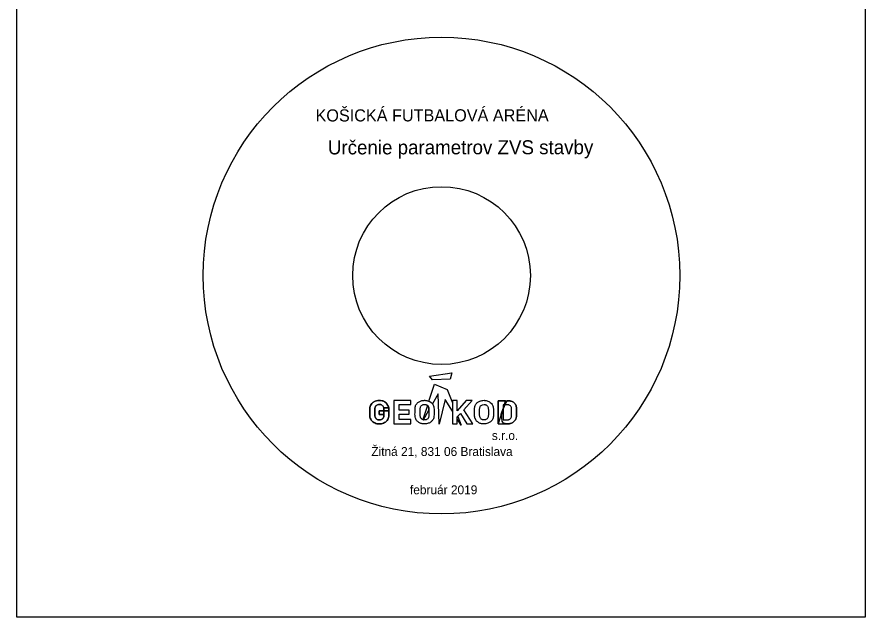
# Model space of a CAD drawing. Extents: x -505246 to -505036, y -1268489 to -1268192.
# Drawn here: x -505246.3 to -505036.3, y -1268489.2 to -1268340.7 of the extents above; entities that cross this region are included whole.
import ezdxf

# ---------------------------------------------------------------- set-up
doc = ezdxf.new("R2010")
doc.units = 0
for name, color, linetype in [('CD_KRUHY', 7, 'Continuous'), ('CD_POPIS', 7, 'Continuous'), ('RAM_NA_TLAC_A4', 7, 'Continuous')]:
    doc.layers.add(name, color=color, linetype=linetype)

msp = doc.modelspace()

# ---------------------------------------------------------------- linework, layer by layer
at = {"layer": 'CD_KRUHY'}
for radius in [59, 22]:
    msp.add_circle((-505141.22, -1268404.66), radius, dxfattribs=at)
at = {"layer": 'CD_POPIS'}
for p, q in [((-505144.36, -1268435.74), (-505142.96, -1268431.5)), ((-505142.96, -1268431.5), (-505139.85, -1268432.82)), ((-505139.85, -1268432.82), (-505138.54, -1268436.16)), ((-505145.5, -1268435.54), (-505145.4, -1268435.53)), ((-505142.07, -1268433.91), (-505143.47, -1268436.41)), ((-505141.8, -1268441.47), (-505142.07, -1268433.91)), ((-505140.31, -1268435.35), (-505141.8, -1268441.47)), ((-505138.54, -1268438.19), (-505140.31, -1268435.35)), ((-505137.32, -1268435.61), (-505138.54, -1268435.61)), ((-505135.12, -1268435.61), (-505137.32, -1268438.11)), ((-505137.32, -1268438.11), (-505137.32, -1268435.61)), ((-505135.7, -1268437.91), (-505133.6, -1268435.61)), ((-505133.6, -1268435.61), (-505135.12, -1268435.61)), ((-505127.18, -1268435.63), (-505125.35, -1268435.63)), ((-505127.18, -1268441.33), (-505127.18, -1268435.63)), ((-505127.18, -1268435.63), (-505127.18, -1268441.33)), ((-505125.35, -1268435.63), (-505127.18, -1268435.63)), ((-505154.25, -1268437.38), (-505155.51, -1268437.38)), ((-505155.51, -1268437.38), (-505154.25, -1268437.38)), ((-505144.71, -1268436.79), (-505145.87, -1268440.31)), ((-505145.48, -1268436.56), (-505145.41, -1268436.56)), ((-505145.48, -1268436.56), (-505145.41, -1268436.56)), ((-505138.54, -1268436.16), (-505138.54, -1268438.19)), ((-505125.93, -1268436.62), (-505125.93, -1268440.34)), ((-505125.93, -1268436.62), (-505125.93, -1268440.34)), ((-505137.22, -1268439.51), (-505136.37, -1268441.69)), ((-505133.49, -1268441.33), (-505135.7, -1268437.91)), ((-505136.37, -1268441.69), (-505137.32, -1268440.15)), ((-505134.93, -1268441.33), (-505133.49, -1268441.33))]:
    msp.add_line(p, q, dxfattribs=at)
for points in [[(-505144.2, -1268429.53), (-505138.67, -1268428.74), (-505139.06, -1268430.32), (-505143.47, -1268430.46)], [(-505152.99, -1268435.58), (-505152.99, -1268441.33), (-505148.78, -1268441.33), (-505148.78, -1268440.32), (-505151.73, -1268440.32), (-505151.73, -1268438.94), (-505149.21, -1268438.94), (-505149.21, -1268437.94), (-505151.73, -1268437.94), (-505151.73, -1268436.6), (-505148.78, -1268436.6), (-505148.78, -1268435.58)]]:
    msp.add_lwpolyline(points, close=True, dxfattribs=at)
for points in [[(-505138.54, -1268435.61), (-505138.54, -1268441.33), (-505137.32, -1268441.33), (-505137.32, -1268439.62), (-505136.51, -1268438.76), (-505134.93, -1268441.33)], [(-505144.33, -1268437.96), (-505144.33, -1268437.83), (-505144.34, -1268437.67), (-505144.35, -1268437.53), (-505144.37, -1268437.39), (-505144.41, -1268437.26), (-505144.46, -1268437.12), (-505144.53, -1268436.99), (-505144.62, -1268436.88), (-505144.71, -1268436.79)], [(-505143.47, -1268436.41), (-505143.51, -1268436.36), (-505143.58, -1268436.27), (-505143.65, -1268436.2), (-505143.74, -1268436.13), (-505143.82, -1268436.06), (-505143.91, -1268435.99), (-505143.99, -1268435.94), (-505144.08, -1268435.89), (-505144.18, -1268435.83), (-505144.27, -1268435.78), (-505144.36, -1268435.74)], [(-505155.47, -1268439.07), (-505156.67, -1268439.07), (-505156.67, -1268438.12), (-505154.23, -1268438.12)], [(-505154.23, -1268438.12), (-505156.67, -1268438.12), (-505156.67, -1268439.07), (-505155.47, -1268439.07)], [(-505145.68, -1268440.36), (-505144.33, -1268437.96)], [(-505137.32, -1268440.15), (-505137.32, -1268439.62), (-505137.22, -1268439.51)], [(-505145.87, -1268440.31), (-505145.84, -1268440.32), (-505145.8, -1268440.33), (-505145.77, -1268440.34), (-505145.73, -1268440.35), (-505145.7, -1268440.36), (-505145.68, -1268440.36)]]:
    msp.add_lwpolyline(points, dxfattribs=at)
for points in [[(-505154.23, -1268438.12), (-505154.23, -1268438.85), (-505154.25, -1268439.5), (-505154.38, -1268440.08), (-505154.66, -1268440.54), (-505155.08, -1268440.93), (-505155.53, -1268441.19), (-505156.12, -1268441.34), (-505156.66, -1268441.38), (-505157.22, -1268441.34), (-505157.78, -1268441.15), (-505158.26, -1268440.84), (-505158.63, -1268440.47), (-505158.88, -1268439.96), (-505158.99, -1268439.41), (-505159.01, -1268439.04), (-505159.01, -1268437.9), (-505158.97, -1268437.29), (-505158.8, -1268436.77), (-505158.52, -1268436.32), (-505157.97, -1268435.87), (-505157.37, -1268435.61), (-505156.68, -1268435.54), (-505155.96, -1268435.6), (-505155.19, -1268435.91), (-505154.6, -1268436.47), (-505154.25, -1268437.38), (-505154.23, -1268438.12), (-505154.25, -1268437.38)], [(-505154.25, -1268437.38), (-505154.6, -1268436.47), (-505155.19, -1268435.91), (-505155.96, -1268435.6), (-505156.68, -1268435.54), (-505157.37, -1268435.61), (-505157.97, -1268435.87), (-505158.52, -1268436.32), (-505158.8, -1268436.77), (-505158.97, -1268437.29), (-505159.01, -1268437.9), (-505159.01, -1268439.04), (-505158.99, -1268439.41), (-505158.88, -1268439.96), (-505158.63, -1268440.47), (-505158.26, -1268440.84), (-505157.78, -1268441.15), (-505157.22, -1268441.34), (-505156.66, -1268441.38), (-505156.12, -1268441.34), (-505155.53, -1268441.19), (-505155.08, -1268440.93), (-505154.66, -1268440.54), (-505154.38, -1268440.08), (-505154.25, -1268439.5), (-505154.23, -1268438.85), (-505154.23, -1268438.12), (-505154.25, -1268437.38), (-505154.23, -1268438.12)], [(-505145.4, -1268435.53), (-505145.37, -1268435.53), (-505145.2, -1268435.53), (-505144.88, -1268435.61), (-505144.45, -1268435.68), (-505144.04, -1268435.91), (-505143.67, -1268436.16), (-505143.37, -1268436.52), (-505143.19, -1268436.92), (-505143.08, -1268437.36), (-505143.08, -1268438.05), (-505143.06, -1268438.77), (-505143.08, -1268439.46), (-505143.14, -1268439.91), (-505143.31, -1268440.27), (-505143.52, -1268440.6), (-505143.81, -1268440.85), (-505144.12, -1268441.08), (-505144.5, -1268441.23), (-505144.92, -1268441.36), (-505145.38, -1268441.38), (-505145.81, -1268441.36), (-505146.19, -1268441.32), (-505146.51, -1268441.17), (-505146.82, -1268441), (-505147.12, -1268440.8), (-505147.39, -1268440.53), (-505147.6, -1268440.15), (-505147.75, -1268439.7), (-505147.82, -1268438.95), (-505147.75, -1268438.25), (-505147.79, -1268437.58), (-505147.73, -1268437.2), (-505147.64, -1268436.83), (-505147.46, -1268436.5), (-505147.22, -1268436.22), (-505146.96, -1268435.98), (-505146.63, -1268435.81), (-505146.26, -1268435.64), (-505145.87, -1268435.56), (-505145.61, -1268435.54), (-505145.5, -1268435.54)], [(-505130.68, -1268435.53), (-505131.11, -1268435.56), (-505131.56, -1268435.66), (-505131.93, -1268435.82), (-505132.23, -1268435.99), (-505132.5, -1268436.23), (-505132.72, -1268436.49), (-505132.91, -1268436.84), (-505133.01, -1268437.21), (-505133.06, -1268437.57), (-505133.05, -1268437.97), (-505133.07, -1268439.21), (-505133.02, -1268439.67), (-505132.85, -1268440.18), (-505132.64, -1268440.54), (-505132.41, -1268440.78), (-505132.09, -1268441), (-505131.79, -1268441.17), (-505131.48, -1268441.3), (-505131.1, -1268441.36), (-505130.69, -1268441.38), (-505130.2, -1268441.34), (-505129.76, -1268441.22), (-505129.42, -1268441.07), (-505129.08, -1268440.84), (-505128.81, -1268440.59), (-505128.61, -1268440.29), (-505128.44, -1268439.9), (-505128.37, -1268439.49), (-505128.35, -1268438.99), (-505128.36, -1268437.81), (-505128.38, -1268437.35), (-505128.48, -1268436.94), (-505128.68, -1268436.51), (-505128.94, -1268436.2), (-505129.35, -1268435.9), (-505129.73, -1268435.71), (-505130.17, -1268435.6), (-505130.6, -1268435.53), (-505130.68, -1268435.53), (-505130.68, -1268435.53), (-505130.68, -1268435.53)], [(-505125.35, -1268435.63), (-505124.76, -1268435.63), (-505124.39, -1268435.65), (-505124.11, -1268435.7), (-505123.76, -1268435.82), (-505123.42, -1268436.01), (-505123.08, -1268436.33), (-505122.83, -1268436.69), (-505122.71, -1268437.03), (-505122.63, -1268437.55), (-505122.63, -1268437.81), (-505122.62, -1268438.95), (-505122.64, -1268439.32), (-505122.67, -1268439.63), (-505122.72, -1268439.95), (-505122.88, -1268440.35), (-505123.17, -1268440.71), (-505123.59, -1268441.05), (-505123.93, -1268441.2), (-505124.28, -1268441.3), (-505124.57, -1268441.33), (-505124.68, -1268441.33), (-505127.18, -1268441.33), (-505125.35, -1268435.63), (-505127.18, -1268441.33)], [(-505127.18, -1268441.33), (-505124.68, -1268441.33), (-505124.57, -1268441.33), (-505124.28, -1268441.3), (-505123.93, -1268441.2), (-505123.59, -1268441.05), (-505123.17, -1268440.71), (-505122.88, -1268440.35), (-505122.72, -1268439.95), (-505122.67, -1268439.63), (-505122.64, -1268439.32), (-505122.62, -1268438.95), (-505122.63, -1268437.81), (-505122.63, -1268437.55), (-505122.71, -1268437.03), (-505122.83, -1268436.69), (-505123.08, -1268436.33), (-505123.42, -1268436.01), (-505123.76, -1268435.82), (-505124.11, -1268435.7), (-505124.39, -1268435.65), (-505124.76, -1268435.63), (-505125.35, -1268435.63), (-505127.18, -1268441.33), (-505125.35, -1268435.63)], [(-505155.5, -1268437.38), (-505155.63, -1268437.07), (-505155.9, -1268436.76), (-505156.29, -1268436.58), (-505156.67, -1268436.56), (-505157.05, -1268436.6), (-505157.35, -1268436.78), (-505157.58, -1268437.02), (-505157.69, -1268437.28), (-505157.7, -1268437.67), (-505157.73, -1268438.1), (-505157.74, -1268438.61), (-505157.73, -1268439.21), (-505157.68, -1268439.66), (-505157.51, -1268440.01), (-505157.27, -1268440.22), (-505156.98, -1268440.34), (-505156.68, -1268440.38), (-505156.31, -1268440.36), (-505155.93, -1268440.2), (-505155.66, -1268439.94), (-505155.5, -1268439.64), (-505155.47, -1268439.3), (-505155.47, -1268439.07), (-505155.5, -1268437.38), (-505155.47, -1268439.07)], [(-505155.47, -1268439.07), (-505155.47, -1268439.3), (-505155.5, -1268439.64), (-505155.66, -1268439.94), (-505155.93, -1268440.2), (-505156.31, -1268440.36), (-505156.68, -1268440.38), (-505156.98, -1268440.34), (-505157.27, -1268440.22), (-505157.51, -1268440.01), (-505157.68, -1268439.66), (-505157.73, -1268439.21), (-505157.74, -1268438.61), (-505157.73, -1268438.1), (-505157.7, -1268437.67), (-505157.69, -1268437.28), (-505157.58, -1268437.02), (-505157.35, -1268436.78), (-505157.05, -1268436.6), (-505156.67, -1268436.56), (-505156.29, -1268436.58), (-505155.9, -1268436.76), (-505155.63, -1268437.07), (-505155.5, -1268437.38), (-505155.47, -1268439.07), (-505155.5, -1268437.38)], [(-505145.41, -1268436.56), (-505145.36, -1268436.56), (-505145.23, -1268436.56), (-505145, -1268436.61), (-505144.75, -1268436.74), (-505144.52, -1268436.96), (-505144.38, -1268437.28), (-505144.32, -1268437.63), (-505144.33, -1268438.02), (-505144.32, -1268438.43), (-505144.34, -1268438.85), (-505144.32, -1268439.23), (-505144.37, -1268439.56), (-505144.45, -1268439.86), (-505144.63, -1268440.12), (-505144.91, -1268440.3), (-505145.2, -1268440.38), (-505145.44, -1268440.36), (-505145.65, -1268440.38), (-505145.88, -1268440.32), (-505146.11, -1268440.18), (-505146.33, -1268439.97), (-505146.48, -1268439.66), (-505146.53, -1268439.29), (-505146.51, -1268438.83), (-505146.52, -1268438.33), (-505146.51, -1268437.85), (-505146.5, -1268437.45), (-505146.43, -1268437.14), (-505146.26, -1268436.89), (-505146.03, -1268436.69), (-505145.75, -1268436.57), (-505145.56, -1268436.56), (-505145.48, -1268436.56)], [(-505145.41, -1268436.56), (-505145.36, -1268436.56), (-505145.23, -1268436.56), (-505145, -1268436.61), (-505144.75, -1268436.74), (-505144.52, -1268436.96), (-505144.38, -1268437.28), (-505144.32, -1268437.63), (-505144.33, -1268438.02), (-505144.32, -1268438.43), (-505144.34, -1268438.85), (-505144.32, -1268439.23), (-505144.37, -1268439.56), (-505144.45, -1268439.86), (-505144.63, -1268440.12), (-505144.91, -1268440.3), (-505145.2, -1268440.38), (-505145.44, -1268440.36), (-505145.65, -1268440.38), (-505145.88, -1268440.32), (-505146.11, -1268440.18), (-505146.33, -1268439.97), (-505146.48, -1268439.66), (-505146.53, -1268439.29), (-505146.51, -1268438.83), (-505146.52, -1268438.33), (-505146.51, -1268437.85), (-505146.5, -1268437.45), (-505146.43, -1268437.14), (-505146.26, -1268436.89), (-505146.03, -1268436.69), (-505145.75, -1268436.57), (-505145.56, -1268436.56), (-505145.48, -1268436.56)], [(-505130.7, -1268436.56), (-505131, -1268436.58), (-505131.31, -1268436.71), (-505131.54, -1268436.91), (-505131.69, -1268437.13), (-505131.77, -1268437.45), (-505131.79, -1268437.79), (-505131.8, -1268438.31), (-505131.8, -1268438.9), (-505131.8, -1268439.3), (-505131.74, -1268439.66), (-505131.58, -1268439.97), (-505131.38, -1268440.18), (-505131.16, -1268440.31), (-505130.92, -1268440.37), (-505130.72, -1268440.37), (-505130.52, -1268440.37), (-505130.21, -1268440.29), (-505129.91, -1268440.08), (-505129.75, -1268439.86), (-505129.66, -1268439.57), (-505129.61, -1268439.25), (-505129.61, -1268438.88), (-505129.61, -1268438.41), (-505129.61, -1268437.99), (-505129.62, -1268437.66), (-505129.69, -1268437.25), (-505129.82, -1268436.98), (-505130.04, -1268436.75), (-505130.31, -1268436.61), (-505130.53, -1268436.56), (-505130.7, -1268436.56), (-505130.7, -1268436.56), (-505130.7, -1268436.56)], [(-505125.93, -1268440.34), (-505125.57, -1268440.34), (-505125.19, -1268440.34), (-505124.79, -1268440.34), (-505124.72, -1268440.34), (-505124.57, -1268440.31), (-505124.34, -1268440.19), (-505124.05, -1268439.99), (-505123.91, -1268439.63), (-505123.87, -1268439.25), (-505123.87, -1268438.71), (-505123.87, -1268438.11), (-505123.87, -1268437.61), (-505123.9, -1268437.27), (-505124.03, -1268437.04), (-505124.29, -1268436.8), (-505124.57, -1268436.67), (-505124.96, -1268436.61), (-505125.23, -1268436.61), (-505125.76, -1268436.62), (-505125.93, -1268436.62)], [(-505125.93, -1268440.34), (-505125.57, -1268440.34), (-505125.19, -1268440.34), (-505124.79, -1268440.34), (-505124.72, -1268440.34), (-505124.57, -1268440.31), (-505124.34, -1268440.19), (-505124.05, -1268439.99), (-505123.91, -1268439.63), (-505123.87, -1268439.25), (-505123.87, -1268438.71), (-505123.87, -1268438.11), (-505123.87, -1268437.61), (-505123.9, -1268437.27), (-505124.03, -1268437.04), (-505124.29, -1268436.8), (-505124.57, -1268436.67), (-505124.96, -1268436.61), (-505125.23, -1268436.61), (-505125.76, -1268436.62), (-505125.93, -1268436.62)]]:
    msp.add_open_spline(points, degree=3, dxfattribs=at)
at = {"layer": 'RAM_NA_TLAC_A4'}
for p, q in [((-505246.35, -1268489.16), (-505246.35, -1268192.16)), ((-505036.35, -1268192.16), (-505036.35, -1268489.16)), ((-505036.35, -1268489.16), (-505246.35, -1268489.16))]:
    msp.add_line(p, q, dxfattribs=at)

# ---------------------------------------------------------------- texts
at = {"layer": 'CD_POPIS'}
for s, height, rotation, p in [('KOŠICKÁ FUTBALOVÁ ARÉNA', 3, 0.0456, (-505172.42, -1268366.53)), ('Určenie parametrov ZVS stavby', 3.4676, 0.0456, (-505169.35, -1268374.68)), ('s.r.o.', 2.2, 0.0016, (-505128.76, -1268445.35)), ('Žitná 21, 831 06 Bratislava', 2.2, 0.0016, (-505158.6, -1268449.31)), ('február 2019', 2.2, 0.0016, (-505149.03, -1268458.78))]:
    msp.add_text(s, height=height, rotation=rotation, dxfattribs=at).set_placement(p)

doc.saveas('drawing.dxf')
